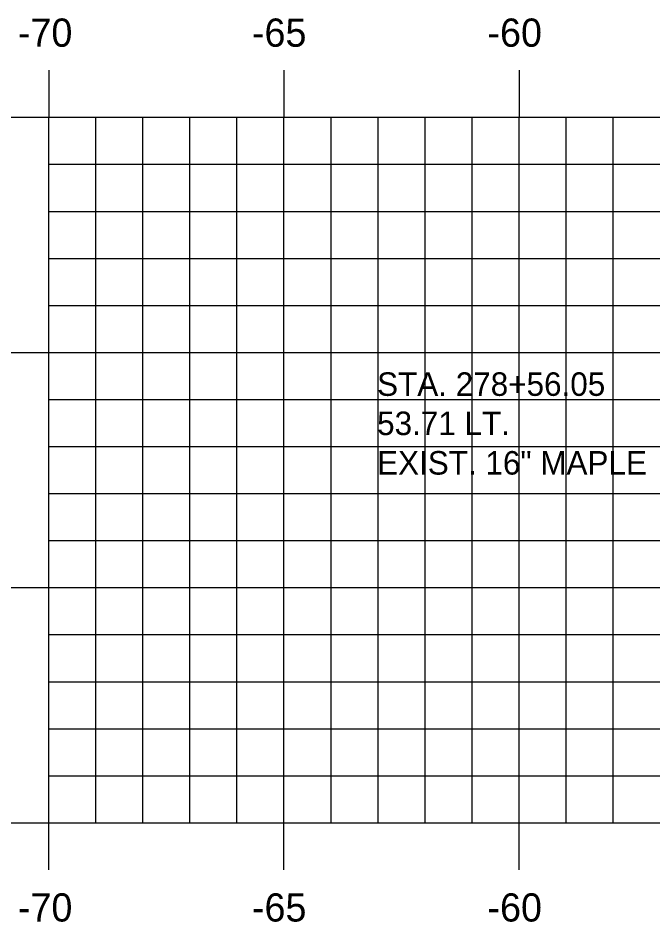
# Model space of a CAD drawing. Extents: x 854676 to 854846, y 366268 to 366378.
# Drawn here: x 854688.45 to 854701.95, y 366300.13 to 366319.35 of the extents above; entities that cross this region are included whole.
import ezdxf

# ---------------------------------------------------------------- set-up
doc = ezdxf.new("R2010")
doc.units = 0
for name, color, linetype in [('D_Text_Monospaced', 7, 'Continuous'), ('H_V ANNOTATION', 7, 'Continuous'), ('MAJOR', 7, 'Continuous'), ('MINOR', 7, 'Continuous')]:
    doc.layers.add(name, color=color, linetype=linetype)

msp = doc.modelspace()

# ---------------------------------------------------------------- linework, layer by layer
at = {"layer": 'MAJOR'}
for p, q in [((854689.106, 366318.238), (854689.106, 366317.236)), ((854694.106, 366318.238), (854694.106, 366317.236)), ((854699.106, 366318.238), (854699.106, 366317.236)), ((854688.104, 366317.236), (854689.106, 366317.236)), ((854689.106, 366317.236), (854829.106, 366317.236)), ((854689.106, 366302.236), (854689.106, 366317.236)), ((854689.106, 366302.236), (854689.106, 366317.236)), ((854689.106, 366317.236), (854829.106, 366317.236)), ((854694.106, 366302.236), (854694.106, 366317.236)), ((854699.106, 366302.236), (854699.106, 366317.236)), ((854688.104, 366312.236), (854689.106, 366312.236)), ((854689.106, 366312.236), (854829.106, 366312.236)), ((854688.104, 366307.236), (854689.106, 366307.236)), ((854689.106, 366307.236), (854829.106, 366307.236)), ((854688.104, 366302.236), (854689.106, 366302.236)), ((854689.106, 366302.236), (854829.106, 366302.236)), ((854689.106, 366302.236), (854829.106, 366302.236)), ((854689.106, 366301.234), (854689.106, 366302.236)), ((854694.106, 366301.234), (854694.106, 366302.236)), ((854699.106, 366301.234), (854699.106, 366302.236))]:
    msp.add_line(p, q, dxfattribs=at)
at = {"layer": 'MINOR'}
for p, q in [((854690.106, 366302.236), (854690.106, 366317.236)), ((854691.106, 366302.236), (854691.106, 366317.236)), ((854692.106, 366302.236), (854692.106, 366317.236)), ((854693.106, 366302.236), (854693.106, 366317.236)), ((854695.106, 366302.236), (854695.106, 366317.236)), ((854696.106, 366302.236), (854696.106, 366317.236)), ((854697.106, 366302.236), (854697.106, 366317.236)), ((854698.106, 366302.236), (854698.106, 366317.236)), ((854700.106, 366302.236), (854700.106, 366317.236)), ((854701.106, 366302.236), (854701.106, 366317.236)), ((854689.106, 366316.236), (854829.106, 366316.236)), ((854689.106, 366316.236), (854690.108, 366316.236)), ((854689.106, 366315.236), (854829.106, 366315.236)), ((854689.106, 366315.236), (854690.108, 366315.236)), ((854689.106, 366314.236), (854829.106, 366314.236)), ((854689.106, 366314.236), (854690.108, 366314.236)), ((854689.106, 366313.236), (854829.106, 366313.236)), ((854689.106, 366313.236), (854690.108, 366313.236)), ((854689.106, 366311.236), (854829.106, 366311.236)), ((854689.106, 366311.236), (854690.108, 366311.236)), ((854689.106, 366310.236), (854829.106, 366310.236)), ((854689.106, 366310.236), (854690.108, 366310.236)), ((854689.106, 366309.236), (854829.106, 366309.236)), ((854689.106, 366309.236), (854690.108, 366309.236)), ((854689.106, 366308.236), (854829.106, 366308.236)), ((854689.106, 366308.236), (854690.108, 366308.236)), ((854689.106, 366306.236), (854829.106, 366306.236)), ((854689.106, 366306.236), (854690.108, 366306.236)), ((854689.106, 366305.236), (854829.106, 366305.236)), ((854689.106, 366305.236), (854690.108, 366305.236)), ((854689.106, 366304.236), (854829.106, 366304.236)), ((854689.106, 366304.236), (854690.108, 366304.236)), ((854689.106, 366303.236), (854829.106, 366303.236)), ((854689.106, 366303.236), (854690.108, 366303.236))]:
    msp.add_line(p, q, dxfattribs=at)

# ---------------------------------------------------------------- texts
at = {"layer": 'D_Text_Monospaced'}
for s, height, p in [('STA. 278+56.05', 0.49998, (854696.086, 366311.313)), ('53.71 LT.', 0.5, (854696.086, 366310.479)), ('EXIST. 16" MAPLE', 0.49998, (854696.086, 366309.639))]:
    msp.add_text(s, height=height, dxfattribs=at).set_placement(p)
at = {"layer": 'H_V ANNOTATION'}
for s, p in [('-70', (854688.448, 366318.736)), ('-65', (854693.424, 366318.736)), ('-60', (854698.432, 366318.736)), ('-70', (854688.448, 366300.136)), ('-65', (854693.424, 366300.136)), ('-60', (854698.432, 366300.136))]:
    msp.add_text(s, height=0.6, dxfattribs=at).set_placement(p)
at = {"layer": 'MAJOR'}
msp.add_text('-', height=0.00000006, rotation=53.1301, dxfattribs=at).set_placement((854689.102, 366302.236))

doc.saveas('drawing.dxf')
